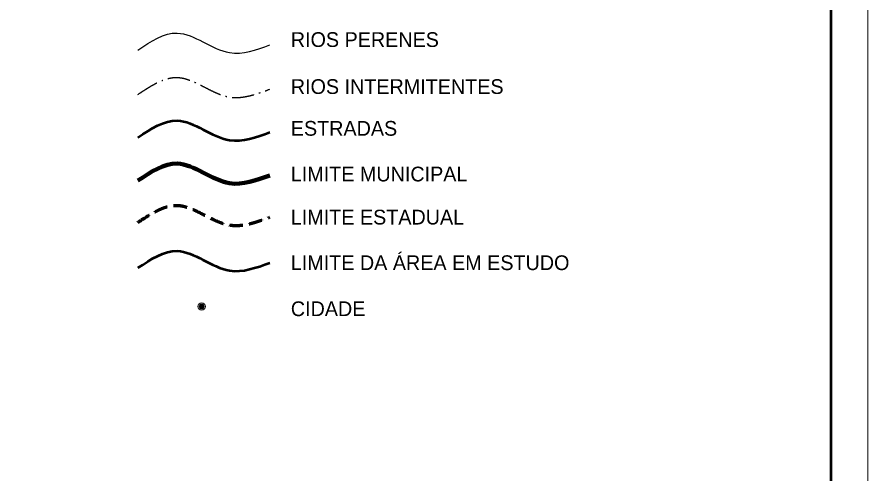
# Model space of a CAD drawing. Extents: x 512883 to 1063249, y 8784064 to 9081064.
# Drawn here: x 947963 to 1063249, y 8846031 to 8907998 of the extents above; entities that cross this region are included whole.
import ezdxf

# ---------------------------------------------------------------- set-up
doc = ezdxf.new("R2010")
doc.units = 0
doc.header["$LTSCALE"] = 600
doc.linetypes.add('DOT_DASHED', pattern=[7.7, 5, -1.2, 0.3, -1.2])
doc.linetypes.add('MEDIUM_DASHED', pattern=[4.5, 3, -1.5])
for name, color, linetype, lineweight in [('1', 7, 'Continuous', 25), ('17', 7, 'Continuous', 13), ('3', 7, 'Continuous', 25)]:
    doc.layers.add(name, color=color, linetype=linetype, lineweight=lineweight)

msp = doc.modelspace()

# ---------------------------------------------------------------- linework, layer by layer
at = {"layer": '1', "lineweight": 13}
for points in [[(512883.1, 8784063.9), (1063248.6, 8784063.9), (1063248.6, 9081063.9), (512883.1, 9081063.9)], [(537883.1, 9076063.9), (1058248.6, 9076063.9), (1058248.6, 8789063.9), (537883.1, 8789063.9)]]:
    msp.add_lwpolyline(points, close=True, dxfattribs=at)
at = {"layer": '1', "lineweight": 53}
msp.add_lwpolyline([(537883.1, 8789063.9), (1058248.6, 8789063.9), (1058248.6, 9076063.9), (537883.1, 9076063.9)], close=True, dxfattribs=at)
at = {"layer": '1'}
msp.add_lwpolyline([(537883.1, 9076063.9), (1058248.6, 9076063.9), (1058248.6, 8789063.9), (537883.1, 8789063.9)], close=True, dxfattribs=at)
at = {"layer": '17'}
for p, q in [((972725.2, 8868967.2), (973225.6, 8868967.2)), ((972754.3, 8868997.2), (973195.9, 8868997.2)), ((972793.9, 8869027.2), (973156.3, 8869027.2)), ((972851.2, 8869057.2), (973099, 8869057.2)), ((972642.7, 8868757.2), (973307.5, 8868757.2)), ((972643.3, 8868727.2), (973307.2, 8868727.2)), ((972644.8, 8868787.2), (973305.4, 8868787.2)), ((972646.3, 8868697.2), (973303.9, 8868697.2)), ((972649.6, 8868817.2), (973300.6, 8868817.2)), ((972652.3, 8868667.2), (973297.9, 8868667.2)), ((972657.7, 8868847.2), (973292.5, 8868847.2)), ((972661.3, 8868637.2), (973288.9, 8868637.2)), ((972668.5, 8868877.2), (973281.7, 8868877.5)), ((972673.9, 8868607.2), (973276.6, 8868607.5)), ((972682.9, 8868907.2), (973267.6, 8868907.2)), ((972689.8, 8868577.2), (973260.4, 8868577.2)), ((972701.2, 8868937.2), (973249.3, 8868937.2)), ((972710.5, 8868547.2), (973240, 8868547.5)), ((972735.7, 8868516.9), (973214.8, 8868517.2)), ((972769, 8868487.2), (973181.2, 8868487.2)), ((972814, 8868457.2), (973136.2, 8868457.2)), ((972887.8, 8868427.2), (973062.1, 8868427.2))]:
    msp.add_line(p, q, dxfattribs=at)
for radius in [506.1, 332.9]:
    msp.add_circle((972975.2, 8868748.2), radius, dxfattribs=at)
at = {"layer": '17', "lineweight": 25}
msp.add_spline([(964351.2, 8903519.8), (969660, 8905821.1), (976738.5, 8903165.8), (982224.3, 8904227.9)], degree=3, dxfattribs=at)
at = {"layer": '17', "linetype": 'DOT_DASHED', "lineweight": 25}
msp.add_spline([(964351.2, 8897501.2), (969660, 8899802.4), (976738.5, 8897147.2), (982224.3, 8898209.3)], degree=3, dxfattribs=at)
at = {"layer": '17', "lineweight": 53}
for points in [[(964351.2, 8891659.6), (969660, 8893960.8), (976738.5, 8891305.5), (982224.3, 8892367.6)], [(964351.2, 8873971.5), (969660, 8876272.7), (976738.5, 8873617.4), (982224.3, 8874679.5)]]:
    msp.add_spline(points, degree=3, dxfattribs=at)
at = {"layer": '17', "lineweight": 90}
msp.add_spline([(964351.2, 8885817.9), (969660, 8888119.2), (976738.5, 8885463.9), (982224.3, 8886526)], degree=3, dxfattribs=at)
at = {"layer": '17', "linetype": 'MEDIUM_DASHED', "lineweight": 70}
msp.add_spline([(964351.2, 8880153.3), (969660, 8882454.6), (976738.5, 8879799.3), (982224.3, 8880861.4)], degree=3, dxfattribs=at)
at = {"layer": '3'}
msp.add_lwpolyline([(537883.1, 9076063.9), (1058248.6, 9076063.9), (1058248.6, 8789063.9), (537883.1, 8789063.9)], close=True, dxfattribs=at)

# ---------------------------------------------------------------- texts
at = {"layer": '17'}
for s, p in [('RIOS PERENES', (985055.7, 8903936)), ('RIOS INTERMITENTES', (985055.7, 8897563.3)), ('ESTRADAS', (985055.7, 8891898.7)), ('LIMITE MUNICIPAL', (985055.7, 8885703)), ('LIMITE ESTADUAL', (985055.7, 8879861.4)), ('LIMITE DA ÁREA EM ESTUDO', (985055.7, 8873679.5)), ('CIDADE', (985055.7, 8867438.1))]:
    msp.add_text(s, height=2000, dxfattribs=at).set_placement(p)

doc.saveas('drawing.dxf')
